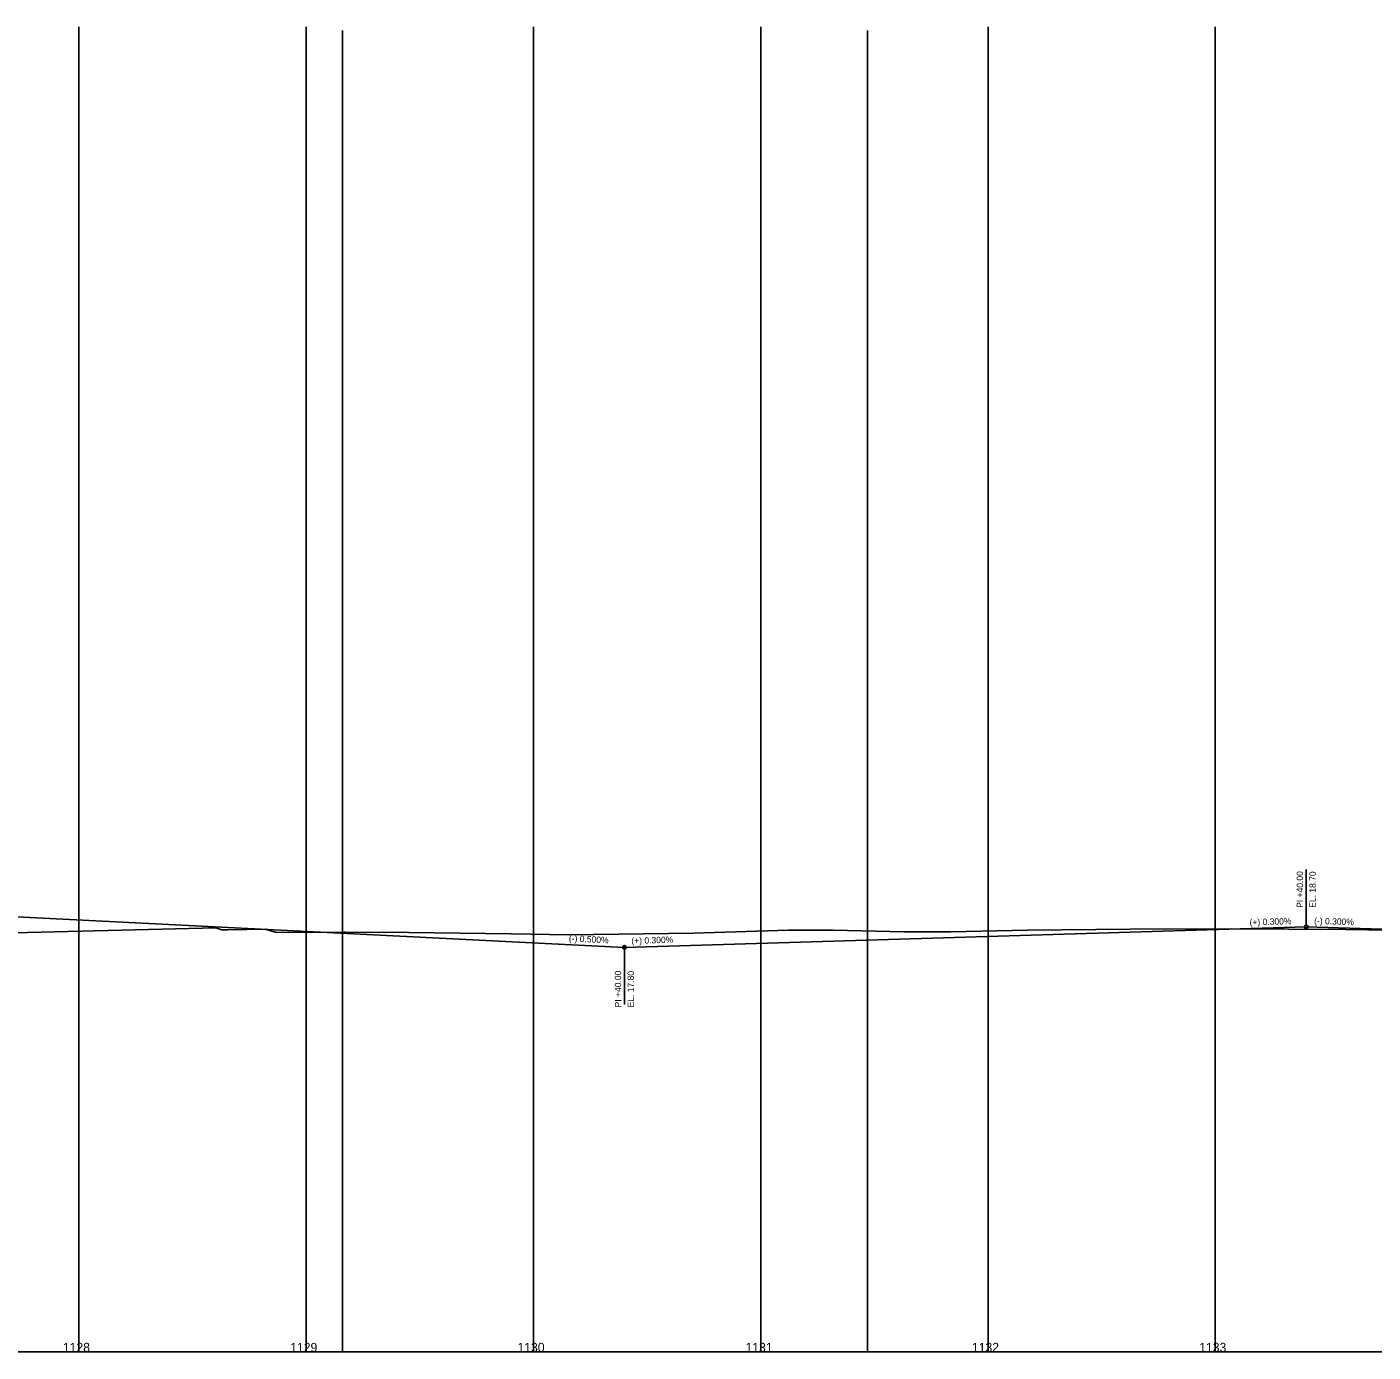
# Model space of a CAD drawing. Extents: x 1409 to 6106, y -2180 to -1584.
# Drawn here: x 2588 to 3180, y -2180 to -1597 of the extents above; entities that cross this region are included whole.
import ezdxf

# ---------------------------------------------------------------- set-up
doc = ezdxf.new("R2010")
doc.units = 0
for name, color, linetype in [('CLConst_dp', 7, 'Continuous'), ('LaneLine', 7, 'Continuous'), ('Miscellaneous0', 7, 'Continuous'), ('NonPlottingEle_dp', 7, 'Continuous'), ('StationTicS_dp', 7, 'Continuous'), ('TextLabel', 7, 'Continuous'), ('TextProfLabel', 7, 'Continuous'), ('TextPtLabel', 7, 'Continuous')]:
    doc.layers.add(name, color=color, linetype=linetype)

msp = doc.modelspace()

# ---------------------------------------------------------------- linework, layer by layer
at = {"layer": 'CLConst_dp'}
msp.add_line((1410.73, -2179.71), (6032.47, -2179.71), dxfattribs=at)
at = {"layer": 'Miscellaneous0'}
for p, q in [((2610.73, -2179.71), (2610.73, -1596.74)), ((2710.73, -2179.71), (2710.73, -1596.74)), ((2810.73, -2179.71), (2810.73, -1596.74)), ((2910.73, -2179.71), (2910.73, -1596.74)), ((3010.73, -2179.71), (3010.73, -1596.74)), ((3110.73, -2179.71), (3110.73, -1596.74))]:
    msp.add_line(p, q, dxfattribs=at)
at = {"layer": 'NonPlottingEle_dp'}
for p, q in [((3150.73, -1991.91), (3150.73, -1967.51)), ((2850.73, -2002.51), (2850.73, -2026.91))]:
    msp.add_line(p, q, dxfattribs=at)
for centre in [(3150.73, -1992.71), (2850.73, -2001.71)]:
    msp.add_circle(centre, 0.8, dxfattribs=at)
at = {"layer": 'StationTicS_dp'}
msp.add_lwpolyline([(2582.27, -1995.38), (2671.02, -1993.11), (2673.54, -1993.97), (2674.87, -1993.96), (2676.29, -1993.93), (2692.73, -1993.71), (2697.61, -1995.24), (2727.47, -1994.96), (2727.98, -1994.97), (2755.86, -1995.21), (2800.98, -1995.8), (2826.27, -1996.19), (2881.18, -1995.47), (2922.91, -1994.12), (2942.66, -1994.21), (2973.9, -1994.9), (2994.38, -1994.82), (3028.17, -1994.11), (3073.27, -1993.77), (3117.83, -1993.55), (3168.35, -1993.8), (3206.04, -1994.48)], dxfattribs=at)
msp.add_lwpolyline([(2582.27, -1995.38), (2671.02, -1993.11), (2673.54, -1993.97), (2674.87, -1993.96), (2676.29, -1993.93), (2692.73, -1993.71), (2697.61, -1995.24), (2727.47, -1994.96), (2727.98, -1994.97), (2755.86, -1995.21), (2800.98, -1995.8), (2826.27, -1996.19), (2881.18, -1995.47), (2922.91, -1994.12), (2942.66, -1994.21), (2973.9, -1994.9), (2994.38, -1994.82), (3028.17, -1994.11), (3073.27, -1993.77), (3117.83, -1993.55), (3168.35, -1993.8), (3206.04, -1994.48)], dxfattribs=at)
at = {"layer": 'TextLabel'}
for p, q in [((2726.73, -2179.71), (2726.73, -1598.37)), ((2957.73, -2179.71), (2957.73, -1598.37))]:
    msp.add_line(p, q, dxfattribs=at)
at = {"layer": 'TextPtLabel'}
for p, q in [((2550.73, -1986.71), (2850.73, -2001.71)), ((2850.73, -2001.71), (3150.73, -1992.71)), ((3150.73, -1992.71), (3400.73, -2000.21))]:
    msp.add_line(p, q, dxfattribs=at)

# ---------------------------------------------------------------- texts
at = {"layer": 'LaneLine'}
for s, rotation, p in [('(+) 0.300%', 1.71836, (3125.86, -1992.06)), ('(-) 0.300%', 358.28164, (3154.2, -1991.42)), ('(-) 0.500%', 357.13759, (2826.26, -1999.09)), ('(+) 0.300%', 1.71836, (2853.85, -2000.22))]:
    msp.add_text(s, height=2.8, rotation=rotation, dxfattribs=at).set_placement(p)
at = {"layer": 'NonPlottingEle_dp'}
for s, p in [('PI +40.00', (3149.33, -1984.31)), ('EL. 18.70', (3154.93, -1984.31)), ('PI +40.00', (2849.33, -2028.11)), ('EL. 17.80', (2854.93, -2028.11))]:
    msp.add_text(s, height=2.8, rotation=90, dxfattribs=at).set_placement(p)
at = {"layer": 'TextProfLabel'}
for s, p in [('1128', (2603.68, -2179.71)), ('1129', (2703.71, -2179.71)), ('1130', (2803.71, -2179.71)), ('1131', (2904.02, -2179.71)), ('1132', (3003.66, -2179.71)), ('1133', (3103.66, -2179.71))]:
    msp.add_text(s, height=4, dxfattribs=at).set_placement(p)

doc.saveas('drawing.dxf')
